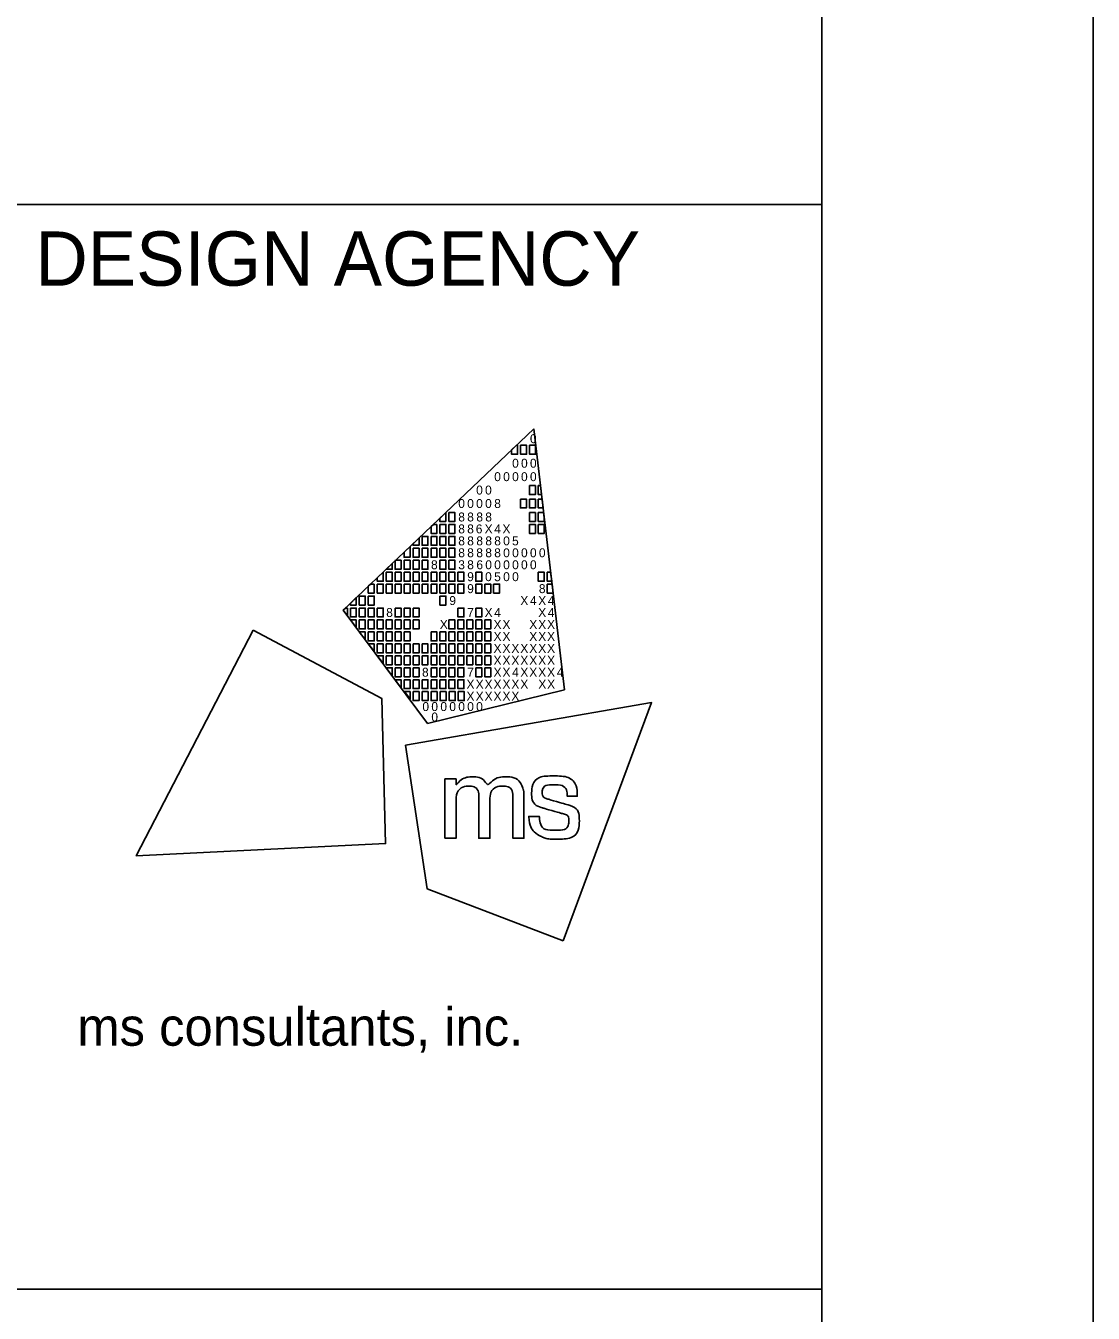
# Model space of a CAD drawing. Extents: x 0 to 34, y 0 to 22.
# Drawn here: x 32.032 to 34, y 2.456 to 4.829 of the extents above; entities that cross this region are included whole.
import ezdxf

# ---------------------------------------------------------------- set-up
doc = ezdxf.new("R2010")
doc.units = 0
for name, color, linetype in [('SH_Border', 7, 'Continuous'), ('SH_Cut_Line', 7, 'Continuous'), ('SH_Data', 7, 'Continuous'), ('SH_Text', 7, 'Continuous')]:
    doc.layers.add(name, color=color, linetype=linetype)

msp = doc.modelspace()

# ---------------------------------------------------------------- linework, layer by layer
at = {"layer": 'SH_Border'}
for p, q in [((32, 4.5), (33.5, 4.5)), ((32, 2.5), (33.5, 2.5))]:
    msp.add_line(p, q, dxfattribs=at)
msp.add_lwpolyline([(1.5, 21.5), (33.5, 21.5), (33.5, 0.5), (1.5, 0.5)], close=True, dxfattribs=at)
at = {"layer": 'SH_Cut_Line'}
msp.add_lwpolyline([(0, 0), (34, 0), (34, 22), (0, 22)], close=True, dxfattribs=at)
at = {"layer": 'SH_Data'}
msp.add_line((32.75, 3.5), (32.75, 3.5), dxfattribs=at)
at = {"layer": 'SH_Text'}
for p, q in [((32.6175, 3.7519), (32.9688, 4.0861)), ((32.9688, 4.0861), (32.9688, 4.0861)), ((32.9688, 4.0861), (33.0253, 3.6052)), ((32.773, 3.543), (32.6175, 3.7519)), ((33.0253, 3.6052), (32.773, 3.543))]:
    msp.add_line(p, q, dxfattribs=at)
for points in [[(32.9279, 4.0472), (32.9369, 4.0558), (32.9389, 4.0558), (32.9389, 4.0393), (32.9279, 4.0393)], [(32.9444, 4.0558), (32.9554, 4.0558), (32.9554, 4.0393), (32.9444, 4.0393)], [(32.9609, 4.0558), (32.9719, 4.0558), (32.9719, 4.0393), (32.9609, 4.0393)], [(32.9606, 3.9815), (32.9716, 3.9815), (32.9716, 3.965), (32.9606, 3.965)], [(32.9771, 3.9815), (32.9811, 3.9815), (32.983, 3.965), (32.9771, 3.965)], [(32.9441, 3.9567), (32.9551, 3.9567), (32.9551, 3.9402), (32.9441, 3.9402)], [(32.9606, 3.9567), (32.9716, 3.9567), (32.9716, 3.9402), (32.9606, 3.9402)], [(32.9771, 3.9567), (32.984, 3.9567), (32.9859, 3.9402), (32.9771, 3.9402)], [(32.7953, 3.9211), (32.8064, 3.9316), (32.8064, 3.9154), (32.7953, 3.9154)], [(32.8123, 3.9319), (32.8233, 3.9319), (32.8233, 3.9154), (32.8123, 3.9154)], [(32.9606, 3.9319), (32.9716, 3.9319), (32.9716, 3.9154), (32.9606, 3.9154)], [(32.9771, 3.9319), (32.9869, 3.9319), (32.9881, 3.9218), (32.9881, 3.9154), (32.9771, 3.9154)], [(32.7958, 3.9099), (32.8068, 3.9099), (32.8068, 3.8934), (32.7958, 3.8934)], [(32.8123, 3.9099), (32.8233, 3.9099), (32.8233, 3.8934), (32.8123, 3.8934)], [(32.9606, 3.9099), (32.9716, 3.9099), (32.9716, 3.8934), (32.9606, 3.8934)], [(32.9771, 3.9099), (32.9881, 3.9099), (32.9881, 3.8934), (32.9771, 3.8934)], [(32.7627, 3.8879), (32.7737, 3.8879), (32.7737, 3.8714), (32.7627, 3.8714)], [(32.7793, 3.8879), (32.7903, 3.8879), (32.7903, 3.8714), (32.7793, 3.8714)], [(32.7958, 3.8879), (32.8068, 3.8879), (32.8068, 3.8714), (32.7958, 3.8714)], [(32.8123, 3.8879), (32.8233, 3.8879), (32.8233, 3.8714), (32.8123, 3.8714)], [(32.7462, 3.8659), (32.7572, 3.8659), (32.7572, 3.8494), (32.7462, 3.8494)], [(32.7627, 3.8659), (32.7737, 3.8659), (32.7737, 3.8494), (32.7627, 3.8494)], [(32.7793, 3.8659), (32.7903, 3.8659), (32.7903, 3.8494), (32.7793, 3.8494)], [(32.7958, 3.8659), (32.8068, 3.8659), (32.8068, 3.8494), (32.7958, 3.8494)], [(32.8123, 3.8659), (32.8233, 3.8659), (32.8233, 3.8494), (32.8123, 3.8494)], [(32.6967, 3.8218), (32.7077, 3.8218), (32.7077, 3.8053), (32.6967, 3.8053)], [(32.7132, 3.8218), (32.7242, 3.8218), (32.7242, 3.8053), (32.7132, 3.8053)], [(32.7297, 3.8439), (32.7407, 3.8439), (32.7407, 3.8273), (32.7297, 3.8273)], [(32.7297, 3.8218), (32.7407, 3.8218), (32.7407, 3.8053), (32.7297, 3.8053)], [(32.7462, 3.8439), (32.7572, 3.8439), (32.7572, 3.8273), (32.7462, 3.8273)], [(32.7462, 3.8218), (32.7572, 3.8218), (32.7572, 3.8053), (32.7462, 3.8053)], [(32.7627, 3.8439), (32.7737, 3.8439), (32.7737, 3.8273), (32.7627, 3.8273)], [(32.7627, 3.8218), (32.7737, 3.8218), (32.7737, 3.8053), (32.7627, 3.8053)], [(32.7793, 3.8218), (32.7903, 3.8218), (32.7903, 3.8053), (32.7793, 3.8053)], [(32.7958, 3.8439), (32.8068, 3.8439), (32.8068, 3.8273), (32.7958, 3.8273)], [(32.7958, 3.8218), (32.8068, 3.8218), (32.8068, 3.8053), (32.7958, 3.8053)], [(32.8123, 3.8439), (32.8233, 3.8439), (32.8233, 3.8273), (32.8123, 3.8273)], [(32.8123, 3.8218), (32.8233, 3.8218), (32.8233, 3.8053), (32.8123, 3.8053)], [(32.8288, 3.8218), (32.8398, 3.8218), (32.8398, 3.8053), (32.8288, 3.8053)], [(32.8618, 3.8218), (32.8728, 3.8218), (32.8728, 3.8053), (32.8618, 3.8053)], [(32.9771, 3.8218), (32.9881, 3.8218), (32.9881, 3.8053), (32.9771, 3.8053)], [(32.9935, 3.8218), (32.9998, 3.8218), (33.0018, 3.8053), (32.9935, 3.8053)], [(32.6802, 3.7998), (32.6912, 3.7998), (32.6912, 3.7833), (32.6802, 3.7833)], [(32.6967, 3.7998), (32.7077, 3.7998), (32.7077, 3.7833), (32.6967, 3.7833)], [(32.7132, 3.7998), (32.7242, 3.7998), (32.7242, 3.7833), (32.7132, 3.7833)], [(32.7297, 3.7998), (32.7407, 3.7998), (32.7407, 3.7833), (32.7297, 3.7833)], [(32.7462, 3.7998), (32.7572, 3.7998), (32.7572, 3.7833), (32.7462, 3.7833)], [(32.7627, 3.7998), (32.7737, 3.7998), (32.7737, 3.7833), (32.7627, 3.7833)], [(32.7793, 3.7998), (32.7903, 3.7998), (32.7903, 3.7833), (32.7793, 3.7833)], [(32.7958, 3.7998), (32.8068, 3.7998), (32.8068, 3.7833), (32.7958, 3.7833)], [(32.8123, 3.7998), (32.8233, 3.7998), (32.8233, 3.7833), (32.8123, 3.7833)], [(32.8288, 3.7998), (32.8398, 3.7998), (32.8398, 3.7833), (32.8288, 3.7833)], [(32.8618, 3.7998), (32.8728, 3.7998), (32.8728, 3.7833), (32.8618, 3.7833)], [(32.8783, 3.7998), (32.8893, 3.7998), (32.8893, 3.7833), (32.8783, 3.7833)], [(32.8947, 3.7998), (32.9057, 3.7998), (32.9057, 3.7833), (32.8947, 3.7833)], [(32.9935, 3.7998), (33.0024, 3.7998), (33.0044, 3.7833), (32.9935, 3.7833)], [(32.6471, 3.7778), (32.6581, 3.7778), (32.6581, 3.7613), (32.6471, 3.7613)], [(32.6637, 3.7778), (32.6747, 3.7778), (32.6747, 3.7613), (32.6637, 3.7613)], [(32.7958, 3.7778), (32.8068, 3.7778), (32.8068, 3.7613), (32.7958, 3.7613)], [(32.6306, 3.7558), (32.6416, 3.7558), (32.6416, 3.7393), (32.6306, 3.7393)], [(32.6471, 3.7558), (32.6581, 3.7558), (32.6581, 3.7393), (32.6471, 3.7393)], [(32.6637, 3.7558), (32.6747, 3.7558), (32.6747, 3.7393), (32.6637, 3.7393)], [(32.6802, 3.7558), (32.6912, 3.7558), (32.6912, 3.7393), (32.6802, 3.7393)], [(32.7132, 3.7558), (32.7242, 3.7558), (32.7242, 3.7393), (32.7132, 3.7393)], [(32.7297, 3.7558), (32.7407, 3.7558), (32.7407, 3.7393), (32.7297, 3.7393)], [(32.7462, 3.7558), (32.7572, 3.7558), (32.7572, 3.7393), (32.7462, 3.7393)], [(32.8288, 3.7558), (32.8398, 3.7558), (32.8398, 3.7393), (32.8288, 3.7393)], [(32.8618, 3.7558), (32.8728, 3.7558), (32.8728, 3.7393), (32.8618, 3.7393)], [(32.6306, 3.7338), (32.6416, 3.7338), (32.6416, 3.72)], [(32.6471, 3.7338), (32.6581, 3.7338), (32.6581, 3.7173), (32.6471, 3.7173)], [(32.6637, 3.7338), (32.6747, 3.7338), (32.6747, 3.7173), (32.6637, 3.7173)], [(32.6802, 3.7338), (32.6912, 3.7338), (32.6912, 3.7173), (32.6802, 3.7173)], [(32.6967, 3.7338), (32.7077, 3.7338), (32.7077, 3.7173), (32.6967, 3.7173)], [(32.7132, 3.7338), (32.7242, 3.7338), (32.7242, 3.7173), (32.7132, 3.7173)], [(32.7297, 3.7338), (32.7407, 3.7338), (32.7407, 3.7173), (32.7297, 3.7173)], [(32.7462, 3.7338), (32.7572, 3.7338), (32.7572, 3.7173), (32.7462, 3.7173)], [(32.8123, 3.7338), (32.8233, 3.7338), (32.8233, 3.7173), (32.8123, 3.7173)], [(32.8288, 3.7338), (32.8398, 3.7338), (32.8398, 3.7173), (32.8288, 3.7173)], [(32.8453, 3.7338), (32.8563, 3.7338), (32.8563, 3.7173), (32.8453, 3.7173)], [(32.8618, 3.7338), (32.8728, 3.7338), (32.8728, 3.7173), (32.8618, 3.7173)], [(32.8783, 3.7338), (32.8893, 3.7338), (32.8893, 3.7173), (32.8783, 3.7173)], [(32.6471, 3.7117), (32.6581, 3.7117), (32.6581, 3.698)], [(32.6637, 3.7117), (32.6747, 3.7117), (32.6747, 3.6952), (32.6637, 3.6952)], [(32.6802, 3.7117), (32.6912, 3.7117), (32.6912, 3.6952), (32.6802, 3.6952)], [(32.6967, 3.7117), (32.7077, 3.7117), (32.7077, 3.6952), (32.6967, 3.6952)], [(32.7132, 3.7117), (32.7242, 3.7117), (32.7242, 3.6952), (32.7132, 3.6952)], [(32.7297, 3.7117), (32.7407, 3.7117), (32.7407, 3.6952), (32.7297, 3.6952)], [(32.7793, 3.7117), (32.7903, 3.7117), (32.7903, 3.6952), (32.7793, 3.6952)], [(32.7958, 3.7117), (32.8068, 3.7117), (32.8068, 3.6952), (32.7958, 3.6952)], [(32.8123, 3.7117), (32.8233, 3.7117), (32.8233, 3.6952), (32.8123, 3.6952)], [(32.8288, 3.7117), (32.8398, 3.7117), (32.8398, 3.6952), (32.8288, 3.6952)], [(32.8453, 3.7117), (32.8563, 3.7117), (32.8563, 3.6952), (32.8453, 3.6952)], [(32.8618, 3.7117), (32.8728, 3.7117), (32.8728, 3.6952), (32.8618, 3.6952)], [(32.8783, 3.7117), (32.8893, 3.7117), (32.8893, 3.6952), (32.8783, 3.6952)], [(32.6637, 3.6897), (32.6747, 3.6897), (32.6747, 3.676)], [(32.6747, 3.6897), (32.6747, 3.6897), (32.6747, 3.6897)], [(32.6802, 3.6897), (32.6912, 3.6897), (32.6912, 3.6732), (32.6802, 3.6732)], [(32.6967, 3.6897), (32.7077, 3.6897), (32.7077, 3.6732), (32.6967, 3.6732)], [(32.7132, 3.6897), (32.7242, 3.6897), (32.7242, 3.6732), (32.7132, 3.6732)], [(32.7297, 3.6897), (32.7407, 3.6897), (32.7407, 3.6732), (32.7297, 3.6732)], [(32.7462, 3.6897), (32.7572, 3.6897), (32.7572, 3.6732), (32.7462, 3.6732)], [(32.7627, 3.6897), (32.7737, 3.6897), (32.7737, 3.6732), (32.7627, 3.6732)], [(32.7793, 3.6897), (32.7903, 3.6897), (32.7903, 3.6732), (32.7793, 3.6732)], [(32.7958, 3.6897), (32.8068, 3.6897), (32.8068, 3.6732), (32.7958, 3.6732)], [(32.8123, 3.6897), (32.8233, 3.6897), (32.8233, 3.6732), (32.8123, 3.6732)], [(32.8288, 3.6897), (32.8398, 3.6897), (32.8398, 3.6732), (32.8288, 3.6732)], [(32.8453, 3.6897), (32.8563, 3.6897), (32.8563, 3.6732), (32.8453, 3.6732)], [(32.8618, 3.6897), (32.8728, 3.6897), (32.8728, 3.6732), (32.8618, 3.6732)], [(32.8783, 3.6897), (32.8893, 3.6897), (32.8893, 3.6732), (32.8783, 3.6732)], [(32.6802, 3.6677), (32.6912, 3.6677), (32.6912, 3.654)], [(32.6967, 3.6677), (32.7077, 3.6677), (32.7077, 3.6512), (32.6967, 3.6512)], [(32.7132, 3.6677), (32.7242, 3.6677), (32.7242, 3.6512), (32.7132, 3.6512)], [(32.7297, 3.6677), (32.7407, 3.6677), (32.7407, 3.6512), (32.7297, 3.6512)], [(32.7462, 3.6677), (32.7572, 3.6677), (32.7572, 3.6512), (32.7462, 3.6512)], [(32.7627, 3.6677), (32.7737, 3.6677), (32.7737, 3.6512), (32.7627, 3.6512)], [(32.7793, 3.6677), (32.7903, 3.6677), (32.7903, 3.6512), (32.7793, 3.6512)], [(32.7958, 3.6677), (32.8068, 3.6677), (32.8068, 3.6512), (32.7958, 3.6512)], [(32.8123, 3.6677), (32.8233, 3.6677), (32.8233, 3.6512), (32.8123, 3.6512)], [(32.8288, 3.6677), (32.8398, 3.6677), (32.8398, 3.6512), (32.8288, 3.6512)], [(32.8453, 3.6677), (32.8563, 3.6677), (32.8563, 3.6512), (32.8453, 3.6512)], [(32.8618, 3.6677), (32.8728, 3.6677), (32.8728, 3.6512), (32.8618, 3.6512)], [(32.8783, 3.6677), (32.8893, 3.6677), (32.8893, 3.6512), (32.8783, 3.6512)], [(32.7077, 3.6305), (32.6965, 3.6457), (32.7077, 3.6457)], [(32.7132, 3.6457), (32.7242, 3.6457), (32.7242, 3.6292), (32.7132, 3.6292)], [(32.7297, 3.6457), (32.7407, 3.6457), (32.7407, 3.6292), (32.7297, 3.6292)], [(32.7462, 3.6457), (32.7572, 3.6457), (32.7572, 3.6292), (32.7462, 3.6292)], [(32.7793, 3.6457), (32.7903, 3.6457), (32.7903, 3.6292), (32.7793, 3.6292)], [(32.7958, 3.6457), (32.8068, 3.6457), (32.8068, 3.6292), (32.7958, 3.6292)], [(32.8123, 3.6457), (32.8233, 3.6457), (32.8233, 3.6292), (32.8123, 3.6292)], [(32.8288, 3.6457), (32.8398, 3.6457), (32.8398, 3.6292), (32.8288, 3.6292)], [(32.8618, 3.6457), (32.8728, 3.6457), (32.8728, 3.6292), (32.8618, 3.6292)], [(32.8783, 3.6457), (32.8893, 3.6457), (32.8893, 3.6292), (32.8783, 3.6292)], [(32.724, 3.6082), (32.7132, 3.6237), (32.7242, 3.6237)], [(32.7297, 3.6237), (32.7407, 3.6237), (32.7407, 3.6072), (32.7297, 3.6072)], [(32.7462, 3.6237), (32.7572, 3.6237), (32.7572, 3.6072), (32.7462, 3.6072)], [(32.7627, 3.6237), (32.7737, 3.6237), (32.7737, 3.6072), (32.7627, 3.6072)], [(32.7793, 3.6237), (32.7903, 3.6237), (32.7903, 3.6072), (32.7793, 3.6072)], [(32.7958, 3.6237), (32.8068, 3.6237), (32.8068, 3.6072), (32.7958, 3.6072)], [(32.8123, 3.6237), (32.8233, 3.6237), (32.8233, 3.6072), (32.8123, 3.6072)], [(32.8288, 3.6237), (32.8398, 3.6237), (32.8398, 3.6072), (32.8288, 3.6072)], [(32.7302, 3.6017), (32.7407, 3.6017), (32.7408, 3.5875)], [(32.7463, 3.6017), (32.7573, 3.6017), (32.7573, 3.5852), (32.7463, 3.5852)], [(32.763, 3.6017), (32.774, 3.6017), (32.774, 3.5852), (32.763, 3.5852)], [(32.7794, 3.6017), (32.7904, 3.6017), (32.7904, 3.5852), (32.7794, 3.5852)], [(32.796, 3.6017), (32.807, 3.6017), (32.807, 3.5852), (32.796, 3.5852)], [(32.8129, 3.6017), (32.8239, 3.6017), (32.8239, 3.5851), (32.8129, 3.5851)], [(32.8296, 3.6017), (32.8406, 3.6017), (32.8406, 3.5851), (32.8296, 3.5851)]]:
    msp.add_lwpolyline(points, close=True, dxfattribs=at)
for points in [[(32.7903, 3.9099), (32.7836, 3.9099), (32.7793, 3.9058), (32.7793, 3.8934), (32.7903, 3.8934), (32.7903, 3.9099)], [(32.7407, 3.8691), (32.7297, 3.8587), (32.7297, 3.8494), (32.7407, 3.8494), (32.7407, 3.8691)], [(32.7572, 3.8849), (32.7462, 3.8744), (32.7462, 3.8714), (32.7572, 3.8714), (32.7572, 3.8849)], [(32.6912, 3.822), (32.6802, 3.8115), (32.6802, 3.8053), (32.6912, 3.8053), (32.6912, 3.822)], [(32.7077, 3.8377), (32.6968, 3.8273), (32.7077, 3.8273), (32.7077, 3.8377)], [(32.7242, 3.8439), (32.7141, 3.8439), (32.7132, 3.843), (32.7132, 3.8273), (32.7242, 3.8273), (32.7242, 3.8439)], [(32.6747, 3.7998), (32.6679, 3.7998), (32.6637, 3.7958), (32.6637, 3.7833), (32.6747, 3.7833), (32.6747, 3.7998)], [(32.6416, 3.7749), (32.6306, 3.7644), (32.6306, 3.7613), (32.6416, 3.7613), (32.6416, 3.7749)], [(32.6251, 3.7558), (32.6216, 3.7558), (32.6175, 3.7519), (32.6251, 3.7417), (32.6251, 3.7558)], [(32.4512, 3.7149), (32.2359, 3.2988), (32.6956, 3.3215), (32.6884, 3.5892), (32.4512, 3.7149)], [(33.0229, 3.1422), (33.1859, 3.5814), (32.7324, 3.5029), (32.7722, 3.2381), (33.0229, 3.1422)]]:
    msp.add_lwpolyline(points, dxfattribs=at)
for points in [[(32.8048, 3.3315), (32.8048, 3.3315), (32.8048, 3.4409), (32.8048, 3.4409), (32.8048, 3.4409), (32.8255, 3.4409), (32.8255, 3.4409), (32.8255, 3.4409), (32.8255, 3.4297), (32.8255, 3.4297), (32.8346, 3.4399), (32.8457, 3.4445), (32.8555, 3.4445), (32.8688, 3.4445), (32.8791, 3.4372), (32.8837, 3.4266), (32.8915, 3.4381), (32.905, 3.4446), (32.9166, 3.4446), (32.9325, 3.4446), (32.9451, 3.435), (32.9494, 3.4213), (32.9494, 3.4212), (32.9494, 3.4212), (32.9494, 3.4212), (32.9501, 3.419), (32.9506, 3.4172), (32.9506, 3.4071), (32.9506, 3.4071), (32.9506, 3.3314), (32.9506, 3.3314), (32.9506, 3.3314), (32.9303, 3.3314), (32.9303, 3.3314), (32.9303, 3.3314), (32.9303, 3.4048), (32.9303, 3.4048), (32.9303, 3.4201), (32.9219, 3.4274), (32.911, 3.4274), (32.8995, 3.4274), (32.8879, 3.4171), (32.8879, 3.4001), (32.8879, 3.4001), (32.8879, 3.3315), (32.8879, 3.3315), (32.8879, 3.3315), (32.8674, 3.3315), (32.8674, 3.3315), (32.8674, 3.3315), (32.8674, 3.4059), (32.8674, 3.4059), (32.8674, 3.4203), (32.8588, 3.4274), (32.8496, 3.4274), (32.8384, 3.4274), (32.8254, 3.417), (32.8254, 3.3962), (32.8254, 3.3962), (32.8254, 3.3315), (32.8254, 3.3315), (32.8254, 3.3315), (32.8048, 3.3315), (32.8048, 3.3315)], [(32.9595, 3.3709), (32.9595, 3.3709), (32.9595, 3.3717), (32.9595, 3.3717), (32.9595, 3.3717), (32.9603, 3.3717), (32.9603, 3.3717), (32.9603, 3.3717), (32.9783, 3.3717), (32.9783, 3.3717), (32.9783, 3.3717), (32.9789, 3.3717), (32.9789, 3.3717), (32.9789, 3.3717), (32.979, 3.371), (32.979, 3.371), (32.9803, 3.3554), (32.9887, 3.346), (33.009, 3.346), (33.0273, 3.346), (33.0333, 3.3554), (33.0333, 3.3631), (33.0333, 3.3732), (33.0256, 3.3758), (33.0175, 3.378), (33.0175, 3.378), (32.987, 3.3867), (32.987, 3.3867), (32.972, 3.3909), (32.9648, 3.4019), (32.9648, 3.4142), (32.9648, 3.4303), (32.9768, 3.4462), (33.0052, 3.4462), (33.0348, 3.4462), (33.0489, 3.4285), (33.0489, 3.4095), (33.0489, 3.4095), (33.0489, 3.4087), (33.0489, 3.4087), (33.0489, 3.4087), (33.0482, 3.4087), (33.0482, 3.4087), (33.0482, 3.4087), (33.0312, 3.4087), (33.0312, 3.4087), (33.0312, 3.4087), (33.0305, 3.4087), (33.0305, 3.4087), (33.0305, 3.4087), (33.0305, 3.4094), (33.0305, 3.4094), (33.0301, 3.4208), (33.0226, 3.43), (33.0056, 3.43), (32.9891, 3.43), (32.9843, 3.4218), (32.9843, 3.4157), (32.9843, 3.4108), (32.9869, 3.4059), (32.9959, 3.4033), (32.9959, 3.4033), (33.0255, 3.3948), (33.0255, 3.3948), (33.0462, 3.3889), (33.0527, 3.3777), (33.0527, 3.3639), (33.0527, 3.3462), (33.041, 3.3298), (33.0087, 3.3298), (32.9952, 3.3298), (32.9877, 3.3321), (32.9823, 3.3348), (32.969, 3.3414), (32.9609, 3.3536), (32.9595, 3.3709)]]:
    msp.add_open_spline(points, degree=3, dxfattribs=at)

# ---------------------------------------------------------------- texts
at = {"layer": 'SH_Border'}
msp.add_text('ms consultants, inc.', height=0.07, rotation=360, dxfattribs=at).set_placement((32.1273, 2.9489))
at = {"layer": 'SH_Data'}
msp.add_text('DESIGN AGENCY', height=0.1, dxfattribs=at).set_placement((32.05, 4.35))
at = {"layer": 'SH_Text'}
for s, p in [('0', (32.9617, 4.0597)), ('0', (32.9288, 4.0145)), ('0', (32.9452, 4.0145)), ('0', (32.9617, 4.0145)), ('0', (32.8958, 3.9897)), ('0', (32.9123, 3.9897)), ('0', (32.9288, 3.9897)), ('0', (32.9452, 3.9897)), ('0', (32.9617, 3.9897)), ('0', (32.8625, 3.965)), ('0', (32.879, 3.965)), ('0', (32.8295, 3.9402)), ('0', (32.846, 3.9402)), ('0', (32.8625, 3.9402)), ('0', (32.879, 3.9402)), ('8', (32.8958, 3.9402)), ('8', (32.8295, 3.9154)), ('8', (32.846, 3.9154)), ('8', (32.8628, 3.9154)), ('8', (32.8793, 3.9154)), ('8', (32.8295, 3.8934)), ('8', (32.846, 3.8934)), ('6', (32.8618, 3.8934)), ('X', (32.8781, 3.8934)), ('4', (32.8958, 3.8934)), ('X', (32.911, 3.8934)), ('8', (32.8295, 3.8713)), ('8', (32.846, 3.8713)), ('8', (32.8628, 3.8713)), ('8', (32.8794, 3.8713)), ('8', (32.8958, 3.8713)), ('0', (32.9123, 3.8713)), ('5', (32.9287, 3.8713)), ('8', (32.8295, 3.8494)), ('8', (32.846, 3.8494)), ('8', (32.8628, 3.8494)), ('8', (32.8794, 3.8494)), ('8', (32.8958, 3.8494)), ('0', (32.9123, 3.8494)), ('0', (32.9288, 3.8494)), ('0', (32.9452, 3.8494)), ('0', (32.9617, 3.8494)), ('0', (32.9782, 3.8494)), ('8', (32.7793, 3.8273)), ('3', (32.8295, 3.8273)), ('8', (32.846, 3.8273)), ('9', (32.846, 3.8053)), ('6', (32.8629, 3.8273)), ('0', (32.879, 3.8053)), ('0', (32.8793, 3.8273)), ('5', (32.8957, 3.8053)), ('0', (32.8958, 3.8273)), ('0', (32.9123, 3.8273)), ('0', (32.9123, 3.8053)), ('0', (32.9288, 3.8273)), ('0', (32.9288, 3.8053)), ('0', (32.9452, 3.8273)), ('0', (32.9617, 3.8273)), ('9', (32.846, 3.7833)), ('8', (32.9781, 3.7833)), ('9', (32.813, 3.7613)), ('X', (32.9439, 3.7613)), ('4', (32.9617, 3.7613)), ('X', (32.9769, 3.7613)), ('4', (32.9946, 3.7613)), ('8', (32.6967, 3.7393)), ('7', (32.846, 3.7393)), ('X', (32.8781, 3.7393)), ('4', (32.8958, 3.7393)), ('X', (32.9769, 3.7393)), ('4', (32.9946, 3.7393)), ('X', (32.7955, 3.7173)), ('X', (32.8945, 3.7173)), ('X', (32.911, 3.7173)), ('X', (32.9604, 3.7173)), ('X', (32.9769, 3.7173)), ('X', (32.9933, 3.7173)), ('X', (32.8945, 3.6952)), ('X', (32.911, 3.6952)), ('X', (32.9604, 3.6952)), ('X', (32.9769, 3.6952)), ('X', (32.9933, 3.6952)), ('X', (32.8945, 3.6732)), ('X', (32.911, 3.6732)), ('X', (32.9274, 3.6732)), ('X', (32.9439, 3.6732)), ('X', (32.9604, 3.6732)), ('X', (32.9769, 3.6732)), ('X', (32.9933, 3.6732)), ('X', (32.8945, 3.6512)), ('X', (32.911, 3.6512)), ('X', (32.9274, 3.6512)), ('X', (32.9439, 3.6512)), ('X', (32.9604, 3.6512)), ('X', (32.9769, 3.6512)), ('X', (32.9933, 3.6512)), ('8', (32.7627, 3.6292)), ('7', (32.846, 3.6292)), ('X', (32.8945, 3.6292)), ('X', (32.911, 3.6292)), ('4', (32.9288, 3.6292)), ('X', (32.9439, 3.6292)), ('X', (32.9604, 3.6292)), ('X', (32.9769, 3.6292)), ('X', (32.9933, 3.6292)), ('4', (33.0111, 3.6292)), ('X', (32.8447, 3.6072)), ('X', (32.8616, 3.6072)), ('X', (32.878, 3.6072)), ('X', (32.8945, 3.6072)), ('X', (32.911, 3.6072)), ('X', (32.9274, 3.6072)), ('X', (32.9439, 3.6072)), ('X', (32.9771, 3.6072)), ('X', (32.9933, 3.6072)), ('X', (32.8447, 3.5851)), ('X', (32.8616, 3.5851)), ('X', (32.878, 3.5851)), ('X', (32.8945, 3.5851)), ('X', (32.911, 3.5851)), ('X', (32.9274, 3.5851)), ('0', (32.7634, 3.5659)), ('0', (32.7799, 3.5659)), ('0', (32.7799, 3.5467)), ('0', (32.7965, 3.5659)), ('0', (32.813, 3.5659)), ('0', (32.8295, 3.5659)), ('0', (32.846, 3.5659)), ('0', (32.8625, 3.5659))]:
    msp.add_text(s, height=0.0165, rotation=360, dxfattribs=at).set_placement(p)

doc.saveas('drawing.dxf')
